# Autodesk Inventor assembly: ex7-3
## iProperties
Shininess: 3
Length Units: 11272
Angle Units: 11279
Time Units: 11290
Mass Units: 11286
Length Display Precision: 3
Angle Display Precision: 2
Compacted: True
Manager: Lebovitz
Company: Autodesk
Created: 2001-07
Part Number: ex7-3
Document SubType Name: Assembly
Designer: The PD Team
Project: Inventor Samples
Density: 0.0
Volumn: 0.0
Area: 0.0
PropertySet Name: Model Information
Control State: 0
Master: False
Checked Out: False
Author: The PD team
Subject: Inventor Samples
Revision Number: A
